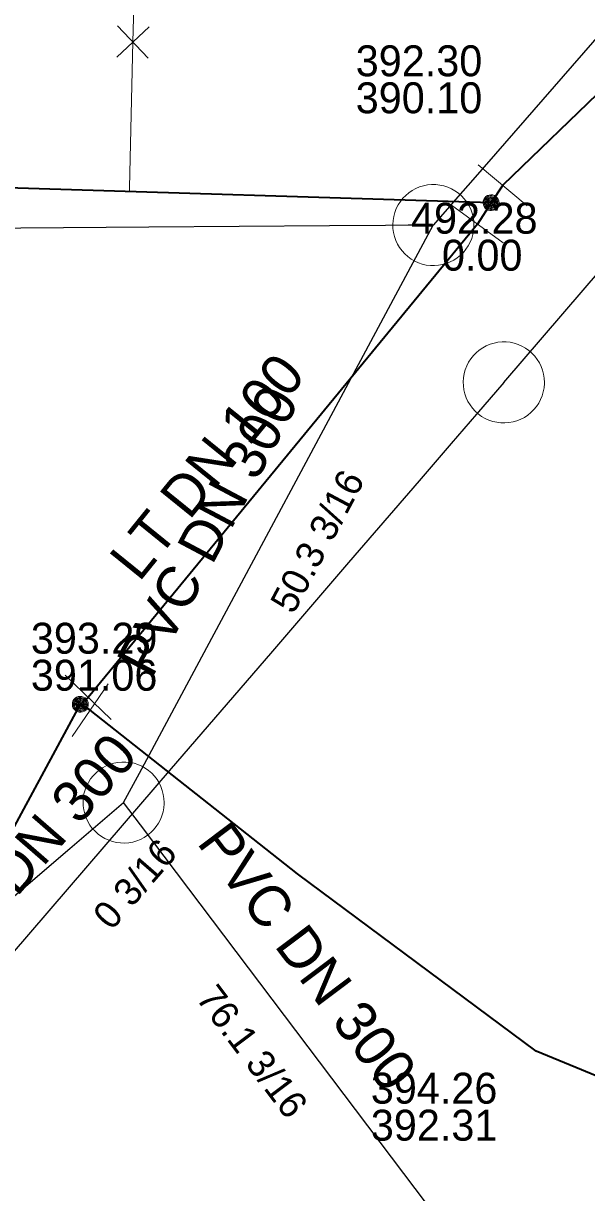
# Model space of a CAD drawing. Extents: x -772952 to -772403, y -1033777 to -1033210.
# Drawn here: x -772788.23 to -772771.85, y -1033340.97 to -1033306.93 of the extents above; entities that cross this region are included whole.
import ezdxf

# ---------------------------------------------------------------- set-up
doc = ezdxf.new("R2010")
doc.units = 0
doc.header["$LTSCALE"] = 0.36
for name, color, linetype, lineweight in [('15', 7, 'Continuous', 13), ('16', 7, 'Continuous', 35), ('2', 7, 'Continuous', 25), ('4', 7, 'Continuous', 13), ('59', 7, 'Continuous', 13)]:
    doc.layers.add(name, color=color, linetype=linetype, lineweight=lineweight)
for name, color, linetype in [('17', 7, 'Continuous'), ('3', 7, 'Continuous'), ('6', 7, 'Continuous')]:
    doc.layers.add(name, color=color, linetype=linetype)

msp = doc.modelspace()

# ---------------------------------------------------------------- linework, layer by layer
at = {"layer": '15'}
for p, q in [((-772785.518, -1033307.911), (-772784.578, -1033307.027)), ((-772784.604, -1033307.942), (-772785.497, -1033306.995)), ((-772773.577, -1033312.237), (-772775.007, -1033311.044)), ((-772774.276, -1033313.318), (-772775.782, -1033312.224)), ((-772785.682, -1033327.198), (-772787.017, -1033325.9)), ((-772786.815, -1033327.688), (-772785.764, -1033326.151))]:
    msp.add_line(p, q, dxfattribs=at)
for points in [[(-772774.399, -1033312.148), (-772774.405, -1033312.096), (-772774.422, -1033312.046), (-772774.451, -1033312.002), (-772774.488, -1033311.965), (-772774.533, -1033311.938), (-772774.583, -1033311.921), (-772774.636, -1033311.917), (-772774.688, -1033311.924), (-772774.737, -1033311.943), (-772774.78, -1033311.972), (-772774.816, -1033312.011), (-772774.842, -1033312.056), (-772774.858, -1033312.107), (-772774.861, -1033312.159), (-772774.853, -1033312.211), (-772774.833, -1033312.26), (-772774.802, -1033312.303), (-772774.763, -1033312.337), (-772774.717, -1033312.363), (-772774.666, -1033312.377), (-772774.613, -1033312.379), (-772774.562, -1033312.369), (-772774.514, -1033312.348), (-772774.471, -1033312.317), (-772774.437, -1033312.276), (-772774.413, -1033312.23), (-772774.401, -1033312.179)], [(-772774.429, -1033312.148), (-772774.435, -1033312.099), (-772774.452, -1033312.053), (-772774.48, -1033312.013), (-772774.517, -1033311.981), (-772774.561, -1033311.959), (-772774.609, -1033311.948), (-772774.658, -1033311.948), (-772774.705, -1033311.961), (-772774.748, -1033311.985), (-772774.784, -1033312.018), (-772774.811, -1033312.059), (-772774.827, -1033312.106), (-772774.831, -1033312.155), (-772774.824, -1033312.203), (-772774.805, -1033312.248), (-772774.775, -1033312.288), (-772774.737, -1033312.319), (-772774.693, -1033312.339), (-772774.645, -1033312.349), (-772774.596, -1033312.347), (-772774.549, -1033312.332), (-772774.506, -1033312.307), (-772774.472, -1033312.273), (-772774.446, -1033312.231), (-772774.432, -1033312.184)], [(-772774.459, -1033312.148), (-772774.465, -1033312.103), (-772774.482, -1033312.061), (-772774.51, -1033312.026), (-772774.546, -1033311.999), (-772774.588, -1033311.982), (-772774.633, -1033311.977), (-772774.678, -1033311.983), (-772774.719, -1033312.002), (-772774.754, -1033312.03), (-772774.781, -1033312.067), (-772774.797, -1033312.109), (-772774.801, -1033312.154), (-772774.794, -1033312.199), (-772774.775, -1033312.24), (-772774.746, -1033312.274), (-772774.709, -1033312.3), (-772774.666, -1033312.316), (-772774.621, -1033312.319), (-772774.576, -1033312.311), (-772774.536, -1033312.291), (-772774.502, -1033312.262), (-772774.476, -1033312.224), (-772774.462, -1033312.181)], [(-772774.489, -1033312.148), (-772774.494, -1033312.107), (-772774.512, -1033312.07), (-772774.539, -1033312.039), (-772774.574, -1033312.018), (-772774.614, -1033312.007), (-772774.655, -1033312.009), (-772774.694, -1033312.022), (-772774.728, -1033312.046), (-772774.753, -1033312.078), (-772774.768, -1033312.116), (-772774.771, -1033312.157), (-772774.763, -1033312.197), (-772774.743, -1033312.233), (-772774.714, -1033312.262), (-772774.677, -1033312.281), (-772774.637, -1033312.289), (-772774.596, -1033312.285), (-772774.558, -1033312.27), (-772774.526, -1033312.244), (-772774.503, -1033312.21), (-772774.49, -1033312.171)], [(-772774.519, -1033312.148), (-772774.524, -1033312.112), (-772774.542, -1033312.08), (-772774.568, -1033312.055), (-772774.602, -1033312.04), (-772774.638, -1033312.037), (-772774.673, -1033312.045), (-772774.704, -1033312.065), (-772774.727, -1033312.093), (-772774.74, -1033312.127), (-772774.74, -1033312.164), (-772774.729, -1033312.199), (-772774.708, -1033312.228), (-772774.678, -1033312.249), (-772774.643, -1033312.259), (-772774.606, -1033312.257), (-772774.572, -1033312.243), (-772774.545, -1033312.22), (-772774.526, -1033312.188), (-772774.519, -1033312.153)], [(-772774.549, -1033312.148), (-772774.554, -1033312.117), (-772774.571, -1033312.091), (-772774.597, -1033312.074), (-772774.627, -1033312.067), (-772774.658, -1033312.071), (-772774.685, -1033312.088), (-772774.703, -1033312.112), (-772774.711, -1033312.143), (-772774.707, -1033312.173), (-772774.692, -1033312.201), (-772774.668, -1033312.22), (-772774.638, -1033312.229), (-772774.607, -1033312.226), (-772774.579, -1033312.212), (-772774.559, -1033312.188), (-772774.549, -1033312.159)], [(-772774.579, -1033312.148), (-772774.584, -1033312.124), (-772774.601, -1033312.106), (-772774.624, -1033312.097), (-772774.648, -1033312.1), (-772774.669, -1033312.114), (-772774.68, -1033312.136), (-772774.68, -1033312.161), (-772774.668, -1033312.182), (-772774.648, -1033312.196), (-772774.623, -1033312.199), (-772774.6, -1033312.19), (-772774.584, -1033312.172)], [(-772774.609, -1033312.148), (-772774.614, -1033312.133), (-772774.629, -1033312.127), (-772774.644, -1033312.131), (-772774.651, -1033312.145), (-772774.647, -1033312.16), (-772774.634, -1033312.169), (-772774.619, -1033312.166), (-772774.609, -1033312.154)], [(-772786.348, -1033326.75), (-772786.355, -1033326.698), (-772786.372, -1033326.648), (-772786.401, -1033326.604), (-772786.438, -1033326.567), (-772786.483, -1033326.54), (-772786.532, -1033326.523), (-772786.586, -1033326.519), (-772786.637, -1033326.526), (-772786.686, -1033326.545), (-772786.73, -1033326.574), (-772786.766, -1033326.613), (-772786.792, -1033326.658), (-772786.808, -1033326.709), (-772786.811, -1033326.761), (-772786.803, -1033326.813), (-772786.782, -1033326.862), (-772786.752, -1033326.905), (-772786.713, -1033326.939), (-772786.667, -1033326.965), (-772786.615, -1033326.979), (-772786.563, -1033326.981), (-772786.512, -1033326.971), (-772786.463, -1033326.95), (-772786.421, -1033326.919), (-772786.387, -1033326.878), (-772786.363, -1033326.832), (-772786.35, -1033326.781)], [(-772786.379, -1033326.75), (-772786.385, -1033326.701), (-772786.402, -1033326.655), (-772786.429, -1033326.615), (-772786.467, -1033326.583), (-772786.511, -1033326.561), (-772786.559, -1033326.55), (-772786.608, -1033326.55), (-772786.654, -1033326.563), (-772786.698, -1033326.587), (-772786.733, -1033326.62), (-772786.761, -1033326.661), (-772786.777, -1033326.708), (-772786.781, -1033326.757), (-772786.774, -1033326.805), (-772786.755, -1033326.85), (-772786.725, -1033326.89), (-772786.686, -1033326.921), (-772786.642, -1033326.941), (-772786.595, -1033326.951), (-772786.546, -1033326.949), (-772786.499, -1033326.934), (-772786.456, -1033326.909), (-772786.421, -1033326.875), (-772786.396, -1033326.833), (-772786.382, -1033326.786)], [(-772786.409, -1033326.75), (-772786.414, -1033326.705), (-772786.431, -1033326.663), (-772786.46, -1033326.628), (-772786.495, -1033326.601), (-772786.538, -1033326.584), (-772786.583, -1033326.579), (-772786.627, -1033326.585), (-772786.669, -1033326.604), (-772786.703, -1033326.632), (-772786.73, -1033326.669), (-772786.747, -1033326.711), (-772786.75, -1033326.756), (-772786.744, -1033326.801), (-772786.725, -1033326.842), (-772786.696, -1033326.876), (-772786.659, -1033326.902), (-772786.615, -1033326.918), (-772786.571, -1033326.921), (-772786.526, -1033326.913), (-772786.485, -1033326.893), (-772786.451, -1033326.864), (-772786.426, -1033326.826), (-772786.412, -1033326.783)], [(-772786.439, -1033326.75), (-772786.443, -1033326.709), (-772786.462, -1033326.672), (-772786.489, -1033326.641), (-772786.524, -1033326.62), (-772786.564, -1033326.609), (-772786.605, -1033326.611), (-772786.644, -1033326.624), (-772786.678, -1033326.648), (-772786.703, -1033326.68), (-772786.718, -1033326.718), (-772786.72, -1033326.759), (-772786.713, -1033326.799), (-772786.693, -1033326.835), (-772786.664, -1033326.864), (-772786.627, -1033326.883), (-772786.587, -1033326.891), (-772786.546, -1033326.887), (-772786.507, -1033326.872), (-772786.475, -1033326.846), (-772786.453, -1033326.812), (-772786.44, -1033326.773)], [(-772786.468, -1033326.75), (-772786.473, -1033326.714), (-772786.492, -1033326.682), (-772786.517, -1033326.657), (-772786.551, -1033326.642), (-772786.588, -1033326.639), (-772786.622, -1033326.647), (-772786.654, -1033326.667), (-772786.676, -1033326.695), (-772786.69, -1033326.729), (-772786.69, -1033326.766), (-772786.679, -1033326.801), (-772786.657, -1033326.83), (-772786.627, -1033326.851), (-772786.593, -1033326.861), (-772786.556, -1033326.859), (-772786.522, -1033326.845), (-772786.495, -1033326.822), (-772786.475, -1033326.79), (-772786.468, -1033326.755)], [(-772786.499, -1033326.75), (-772786.504, -1033326.719), (-772786.521, -1033326.693), (-772786.546, -1033326.676), (-772786.576, -1033326.669), (-772786.608, -1033326.673), (-772786.635, -1033326.69), (-772786.652, -1033326.714), (-772786.661, -1033326.745), (-772786.657, -1033326.775), (-772786.642, -1033326.803), (-772786.617, -1033326.822), (-772786.588, -1033326.831), (-772786.556, -1033326.828), (-772786.529, -1033326.814), (-772786.509, -1033326.79), (-772786.499, -1033326.761)], [(-772786.529, -1033326.75), (-772786.534, -1033326.726), (-772786.551, -1033326.708), (-772786.573, -1033326.699), (-772786.598, -1033326.702), (-772786.619, -1033326.716), (-772786.63, -1033326.738), (-772786.63, -1033326.763), (-772786.617, -1033326.784), (-772786.598, -1033326.798), (-772786.573, -1033326.801), (-772786.549, -1033326.792), (-772786.534, -1033326.774)], [(-772786.559, -1033326.75), (-772786.564, -1033326.735), (-772786.578, -1033326.729), (-772786.593, -1033326.733), (-772786.6, -1033326.747), (-772786.597, -1033326.762), (-772786.583, -1033326.771), (-772786.568, -1033326.768), (-772786.559, -1033326.756)]]:
    msp.add_lwpolyline(points, close=True, dxfattribs=at)
at = {"layer": '16'}
for p, q in [((-772774.629, -1033312.147), (-772811.827, -1033311.001)), ((-772774.291, -1033311.64), (-772774.629, -1033312.147)), ((-772774.629, -1033312.147), (-772775.028, -1033312.771)), ((-772775.028, -1033312.771), (-772786.35, -1033326.55)), ((-772786.35, -1033326.55), (-772786.579, -1033326.75)), ((-772786.579, -1033326.75), (-772792.355, -1033337.418)), ((-772786.29, -1033326.92), (-772786.58, -1033326.75))]:
    msp.add_line(p, q, dxfattribs=at)
for points in [[(-772697.486, -1033237.004), (-772702.392, -1033240.537), (-772721.486, -1033259.44), (-772724.793, -1033262.712), (-772726.954, -1033264.853), (-772730.355, -1033268.219), (-772733.767, -1033271.598), (-772743.414, -1033281.146), (-772745.156, -1033282.871), (-772753.92, -1033291.547), (-772763.164, -1033300.699), (-772765.243, -1033302.896), (-772774.291, -1033311.64)], [(-772731.85, -1033345.57), (-772738.079, -1033345.339), (-772742.289, -1033345.19), (-772747.28, -1033344.589), (-772756, -1033342.309), (-772765.059, -1033340.26), (-772773.32, -1033336.85), (-772780.26, -1033331.69), (-772786.289, -1033326.92)]]:
    msp.add_lwpolyline(points, dxfattribs=at)
at = {"layer": '2'}
for points in [[(-772774.26, -1033317.38), (-772766.272, -1033308.08), (-772757.691, -1033298.091), (-772754.673, -1033294.967), (-772747.614, -1033287.734), (-772737.334, -1033277.2), (-772724.53, -1033264.08)], [(-772757.63, -1033291.32), (-772758.112, -1033291.874), (-772758.373, -1033292.175), (-772759.884, -1033293.912), (-772766.704, -1033301.754), (-772767.151, -1033302.269), (-772775.095, -1033311.403), (-772775.663, -1033312.056), (-772775.897, -1033312.326), (-772776.31, -1033312.8)], [(-772776.31, -1033312.8), (-772777.043, -1033312.805), (-772777.699, -1033312.809), (-772779.326, -1033312.821), (-772784.589, -1033312.859), (-772788.311, -1033312.885), (-772790.991, -1033312.904), (-772802.376, -1033312.986), (-772810.876, -1033313.046), (-772816.3, -1033313.085), (-772821.487, -1033313.122), (-772823.628, -1033313.137), (-772826.73, -1033313.16)], [(-772785.32, -1033329.61), (-772784.861, -1033328.754), (-772776.31, -1033312.8)], [(-772774.26, -1033317.38), (-772775.055, -1033318.303), (-772775.793, -1033319.162), (-772776.724, -1033320.243), (-772778.773, -1033322.624), (-772781.051, -1033325.271), (-772783.935, -1033328.623), (-772785.839, -1033330.834), (-772789.162, -1033334.697), (-772791.52, -1033337.436), (-772793.626, -1033339.883), (-772796.031, -1033342.678), (-772798.21, -1033345.21)], [(-772794.79, -1033337.71), (-772786.885, -1033330.948), (-772785.32, -1033329.61)], [(-772775.43, -1033342.71), (-772784.826, -1033330.263), (-772785.32, -1033329.61)]]:
    msp.add_lwpolyline(points, dxfattribs=at)
at = {"layer": '4'}
for points in [[(-772775.129, -1033312.8), (-772775.135, -1033312.681), (-772775.153, -1033312.564), (-772775.182, -1033312.448), (-772775.223, -1033312.337), (-772775.275, -1033312.23), (-772775.338, -1033312.129), (-772775.411, -1033312.034), (-772775.492, -1033311.948), (-772775.582, -1033311.87), (-772775.68, -1033311.801), (-772775.783, -1033311.743), (-772775.892, -1033311.696), (-772776.006, -1033311.659), (-772776.122, -1033311.634), (-772776.24, -1033311.622), (-772776.359, -1033311.621), (-772776.478, -1033311.632), (-772776.594, -1033311.655), (-772776.708, -1033311.689), (-772776.818, -1033311.735), (-772776.923, -1033311.792), (-772777.021, -1033311.859), (-772777.112, -1033311.935), (-772777.195, -1033312.02), (-772777.269, -1033312.114), (-772777.333, -1033312.214), (-772777.387, -1033312.32), (-772777.43, -1033312.431), (-772777.462, -1033312.545), (-772777.481, -1033312.663), (-772777.489, -1033312.782), (-772777.485, -1033312.9), (-772777.469, -1033313.018), (-772777.441, -1033313.134), (-772777.402, -1033313.246), (-772777.351, -1033313.354), (-772777.29, -1033313.456), (-772777.219, -1033313.552), (-772777.139, -1033313.639), (-772777.05, -1033313.719), (-772776.954, -1033313.789), (-772776.851, -1033313.849), (-772776.743, -1033313.898), (-772776.63, -1033313.936), (-772776.514, -1033313.962), (-772776.396, -1033313.977), (-772776.277, -1033313.98), (-772776.159, -1033313.971), (-772776.041, -1033313.95), (-772775.927, -1033313.917), (-772775.817, -1033313.873), (-772775.711, -1033313.818), (-772775.612, -1033313.752), (-772775.519, -1033313.677), (-772775.435, -1033313.593), (-772775.36, -1033313.501), (-772775.294, -1033313.402), (-772775.238, -1033313.297), (-772775.194, -1033313.187), (-772775.16, -1033313.073), (-772775.139, -1033312.956), (-772775.129, -1033312.837)], [(-772773.08, -1033317.379), (-772773.086, -1033317.26), (-772773.104, -1033317.143), (-772773.133, -1033317.027), (-772773.174, -1033316.916), (-772773.226, -1033316.809), (-772773.289, -1033316.708), (-772773.362, -1033316.613), (-772773.443, -1033316.527), (-772773.533, -1033316.449), (-772773.631, -1033316.38), (-772773.734, -1033316.322), (-772773.843, -1033316.275), (-772773.957, -1033316.238), (-772774.073, -1033316.213), (-772774.191, -1033316.201), (-772774.31, -1033316.2), (-772774.429, -1033316.211), (-772774.545, -1033316.234), (-772774.659, -1033316.268), (-772774.769, -1033316.314), (-772774.874, -1033316.371), (-772774.972, -1033316.438), (-772775.063, -1033316.514), (-772775.146, -1033316.599), (-772775.22, -1033316.693), (-772775.284, -1033316.793), (-772775.338, -1033316.899), (-772775.381, -1033317.01), (-772775.413, -1033317.124), (-772775.432, -1033317.242), (-772775.44, -1033317.361), (-772775.436, -1033317.479), (-772775.42, -1033317.597), (-772775.392, -1033317.713), (-772775.353, -1033317.825), (-772775.302, -1033317.933), (-772775.241, -1033318.035), (-772775.17, -1033318.131), (-772775.09, -1033318.218), (-772775.001, -1033318.298), (-772774.905, -1033318.368), (-772774.802, -1033318.428), (-772774.694, -1033318.477), (-772774.581, -1033318.515), (-772774.465, -1033318.541), (-772774.347, -1033318.556), (-772774.228, -1033318.559), (-772774.11, -1033318.55), (-772773.992, -1033318.529), (-772773.878, -1033318.496), (-772773.768, -1033318.452), (-772773.662, -1033318.397), (-772773.563, -1033318.331), (-772773.47, -1033318.256), (-772773.386, -1033318.172), (-772773.311, -1033318.08), (-772773.245, -1033317.981), (-772773.189, -1033317.876), (-772773.145, -1033317.766), (-772773.111, -1033317.652), (-772773.09, -1033317.535), (-772773.08, -1033317.416)], [(-772784.139, -1033329.61), (-772784.146, -1033329.491), (-772784.164, -1033329.374), (-772784.193, -1033329.258), (-772784.233, -1033329.147), (-772784.286, -1033329.04), (-772784.348, -1033328.939), (-772784.421, -1033328.844), (-772784.502, -1033328.758), (-772784.593, -1033328.68), (-772784.691, -1033328.611), (-772784.794, -1033328.553), (-772784.902, -1033328.506), (-772785.017, -1033328.469), (-772785.132, -1033328.444), (-772785.25, -1033328.432), (-772785.37, -1033328.431), (-772785.489, -1033328.442), (-772785.605, -1033328.465), (-772785.718, -1033328.499), (-772785.828, -1033328.545), (-772785.933, -1033328.602), (-772786.032, -1033328.669), (-772786.122, -1033328.745), (-772786.206, -1033328.83), (-772786.279, -1033328.924), (-772786.343, -1033329.024), (-772786.397, -1033329.13), (-772786.441, -1033329.241), (-772786.473, -1033329.355), (-772786.492, -1033329.473), (-772786.5, -1033329.592), (-772786.495, -1033329.71), (-772786.48, -1033329.828), (-772786.451, -1033329.944), (-772786.413, -1033330.056), (-772786.362, -1033330.164), (-772786.301, -1033330.266), (-772786.23, -1033330.362), (-772786.149, -1033330.449), (-772786.061, -1033330.529), (-772785.965, -1033330.599), (-772785.862, -1033330.659), (-772785.754, -1033330.708), (-772785.641, -1033330.746), (-772785.524, -1033330.772), (-772785.407, -1033330.787), (-772785.288, -1033330.79), (-772785.169, -1033330.781), (-772785.051, -1033330.76), (-772784.938, -1033330.727), (-772784.828, -1033330.683), (-772784.722, -1033330.628), (-772784.622, -1033330.562), (-772784.529, -1033330.487), (-772784.446, -1033330.403), (-772784.37, -1033330.311), (-772784.304, -1033330.212), (-772784.249, -1033330.107), (-772784.205, -1033329.997), (-772784.171, -1033329.883), (-772784.149, -1033329.766), (-772784.139, -1033329.647)]]:
    msp.add_lwpolyline(points, close=True, dxfattribs=at)
at = {"layer": '59'}
msp.add_lwpolyline([(-772785.148, -1033311.823), (-772785.145, -1033311.709), (-772785.05, -1033307.469), (-772784.989, -1033305.37)], dxfattribs=at)

# ---------------------------------------------------------------- texts
at = {"layer": '17'}
msp.add_text('LT DN 100 ', height=1.2, rotation=51, dxfattribs=at).set_placement((-772784.867, -1033323.215))
at = {"layer": '3'}
for s, height, rotation, p in [('PVC DN 300', 1.2, 62, (-772784.506, -1033326.033)), ('50.3 3/16', 0.8, 62, (-772780.382, -1033324.158)), ('PVC DN 300', 1.2, 49, (-772790.885, -1033335.207)), ('PVC DN 300', 1.2, 307, (-772783.213, -1033330.784)), ('0 3/16 ', 0.8, 49, (-772785.67, -1033333.362)), ('76.1 3/16', 0.8, 307, (-772783.238, -1033335.313))]:
    msp.add_text(s, height=height, rotation=rotation, dxfattribs=at).set_placement(p)
at = {"layer": '6'}
for s, p in [('392.30', (-772778.567, -1033308.467)), ('390.10', (-772778.567, -1033309.544)), ('492.28', (-772776.959, -1033313.049)), ('0.00', (-772776.059, -1033314.126)), ('393.29', (-772788.018, -1033325.277)), ('391.06', (-772788.018, -1033326.354)), ('394.26', (-772778.128, -1033338.377)), ('392.31', (-772778.128, -1033339.454))]:
    msp.add_text(s, height=0.9, dxfattribs=at).set_placement(p)

doc.saveas('drawing.dxf')
